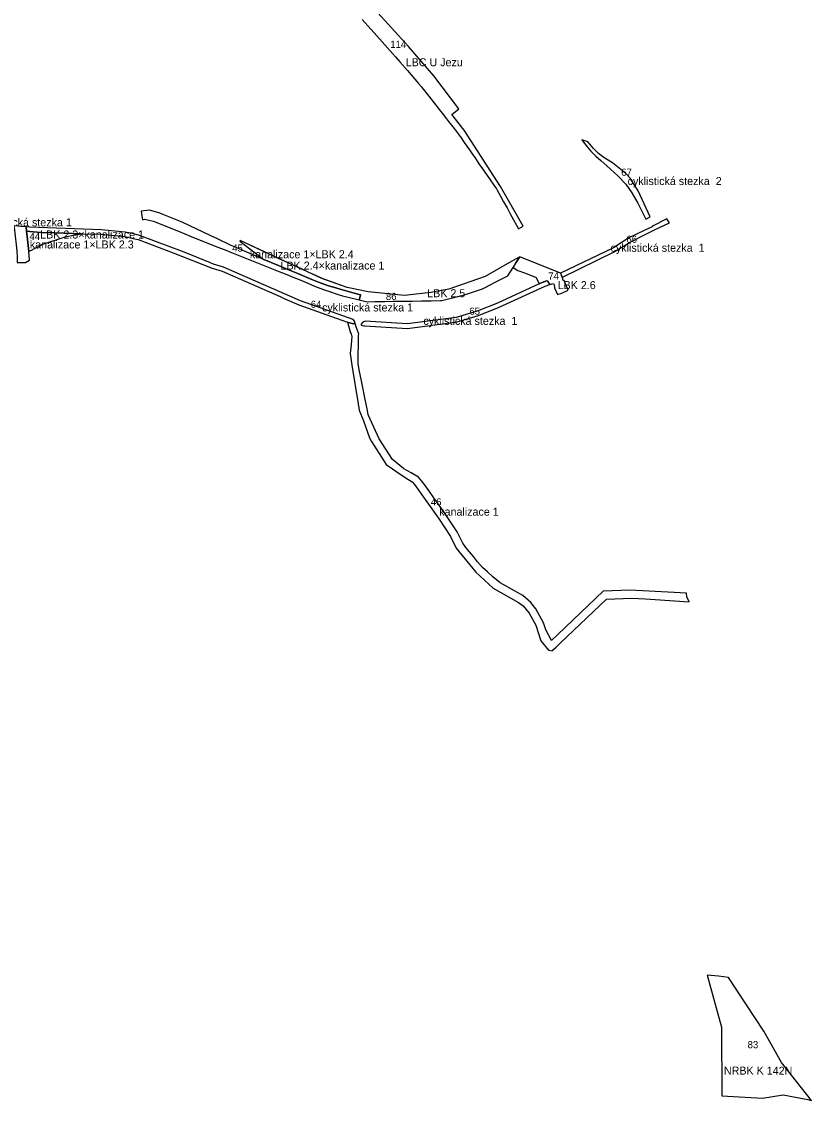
# Model space of a CAD drawing. Extents: x -535270 to -532834, y -1165802 to -1163869.
# Drawn here: x -533722 to -532834, y -1165802 to -1164589 of the extents above; entities that cross this region are included whole.
import ezdxf

# ---------------------------------------------------------------- set-up
doc = ezdxf.new("R2010")
doc.units = 0
for name, color, linetype in [('Level 51', 7, 'Continuous'), ('Level 57', 7, 'Continuous'), ('Level 59', 7, 'Continuous'), ('Level 60', 7, 'Continuous'), ('Level 61', 7, 'Continuous'), ('Level 62', 7, 'Continuous')]:
    doc.layers.add(name, color=color, linetype=linetype)

msp = doc.modelspace()

# ---------------------------------------------------------------- linework, layer by layer
at = {"layer": 'Level 51'}
for points in [[(-533076.2, -1164740.6), (-533070.5, -1164745.6), (-533063.9, -1164751.8), (-533051.6, -1164762.9), (-533042.4, -1164772.1), (-533035.7, -1164782.1), (-533028.9, -1164793.4), (-533020.2, -1164811.4), (-533015, -1164809.1), (-533028.6, -1164779.9), (-533037.8, -1164765.4), (-533042.7, -1164760.3), (-533057.7, -1164748.3), (-533059.3, -1164747.3), (-533067.1, -1164742.2), (-533073.2, -1164737.6), (-533078.8, -1164732.3), (-533082.7, -1164727.8), (-533085.2, -1164724.6), (-533088.7, -1164723.5), (-533092, -1164722.5), (-533090.2, -1164724.9), (-533085.8, -1164730.7), (-533081.8, -1164735.2), (-533076.2, -1164740.6)], [(-533508.9, -1164830.2), (-533541.2, -1164814.8), (-533558, -1164808.3), (-533563.9, -1164806), (-533566.5, -1164805), (-533577.8, -1164801.3), (-533587.3, -1164802.7), (-533586.5, -1164807.8), (-533585.8, -1164812.2), (-533583.6, -1164811.6), (-533573.3, -1164813.9), (-533568.8, -1164815.7), (-533545.2, -1164825.2), (-533531.1, -1164830.9), (-533502.4, -1164842.5), (-533497.2, -1164844.5), (-533491.2, -1164846.9), (-533487.7, -1164848.3), (-533431.5, -1164870.6), (-533428.4, -1164871.8), (-533423.5, -1164873.9), (-533415.9, -1164877.1), (-533408, -1164880.3), (-533400.1, -1164883.6), (-533392.6, -1164886.7), (-533386.5, -1164889.3), (-533381.4, -1164891), (-533373.5, -1164893.7), (-533369.1, -1164895.3), (-533366, -1164896.3), (-533360.9, -1164897.6), (-533353.2, -1164899.6), (-533343.8, -1164902), (-533342.3, -1164902.3), (-533341.7, -1164900), (-533340.8, -1164896.5), (-533348, -1164894.6), (-533355.6, -1164892.4), (-533363.8, -1164890.2), (-533368.5, -1164888.9), (-533376.8, -1164886.6), (-533387.9, -1164882.2), (-533395.4, -1164879.2), (-533403.4, -1164875.9), (-533411.2, -1164872.7), (-533418.9, -1164869.5), (-533426.8, -1164866.3), (-533432.8, -1164863.8), (-533449.3, -1164857), (-533482.5, -1164842.7), (-533486, -1164841.2), (-533502.2, -1164833.4), (-533508.9, -1164830.2)], [(-533012.9, -1164819.8), (-533013.1, -1164820), (-533021.8, -1164824.2), (-533039.3, -1164832.6), (-533056.5, -1164843.9), (-533116, -1164872.2), (-533114.8, -1164874.6), (-533114.4, -1164876.7), (-533113.9, -1164876.6), (-533055.7, -1164848.2), (-533054.7, -1164847.5), (-533037.7, -1164837.5), (-533037.4, -1164837.3), (-533036.8, -1164837), (-533019.4, -1164828.2), (-533011, -1164824), (-533010.3, -1164823.7), (-532993.6, -1164815.7), (-532996.3, -1164811.1), (-533011.7, -1164819.2), (-533012.9, -1164819.8)]]:
    msp.add_lwpolyline(points, dxfattribs=at)
for points in [[(-533425.9, -1164901), (-533410.2, -1164907.9), (-533368.1, -1164922.8), (-533355.4, -1164927.2), (-533349, -1164929.4), (-533346.6, -1164929), (-533347.4, -1164926.2), (-533349.1, -1164924.4), (-533390.2, -1164909.9), (-533408.4, -1164903.2), (-533494.7, -1164865.5), (-533506.1, -1164862), (-533509.4, -1164860.7), (-533541, -1164848), (-533589.2, -1164829.8), (-533593.1, -1164828.7), (-533598.9, -1164827.3), (-533603.5, -1164826.4), (-533605.3, -1164826.1), (-533632, -1164823.5), (-533712.8, -1164820.5), (-533716.6, -1164820.2), (-533716.1, -1164825.2), (-533708.7, -1164825.9), (-533699.2, -1164826.6), (-533684.5, -1164827), (-533654.5, -1164827.9), (-533632.4, -1164828.5), (-533605.8, -1164831.1), (-533596.5, -1164833.2), (-533590.8, -1164834.6), (-533551.4, -1164849.4), (-533507.7, -1164866.7), (-533496.4, -1164870.2), (-533431.1, -1164898.6)], [(-533704.3, -1164843), (-533700.8, -1164841.2), (-533699, -1164840.2), (-533671.6, -1164831.2), (-533654.5, -1164827.9), (-533684.5, -1164827), (-533699.2, -1164826.6), (-533708.7, -1164825.9), (-533716.1, -1164825.2), (-533716.1, -1164825.6), (-533715.5, -1164831), (-533713.8, -1164847.9)], [(-533133.3, -1164886.8), (-533127.9, -1164885.1), (-533130.3, -1164881.4), (-533131.8, -1164880.8), (-533136.5, -1164882.7), (-533140, -1164884.3), (-533186.9, -1164906.1), (-533209.6, -1164915), (-533233.2, -1164922.1), (-533288, -1164929.4), (-533335.4, -1164926.4), (-533338.3, -1164927.4), (-533340, -1164929.7), (-533340.1, -1164930.7), (-533337.2, -1164931.5), (-533335.9, -1164931.4), (-533287.8, -1164934.4), (-533232.1, -1164927), (-533208, -1164919.7), (-533184.9, -1164910.6)], [(-533330.5, -1165057.3), (-533328.6, -1165061.6), (-533311.9, -1165087.2), (-533304.7, -1165092.2), (-533299.9, -1165095.6), (-533290.7, -1165102), (-533282.9, -1165107), (-533280, -1165109.9), (-533252.3, -1165148.7), (-533239.7, -1165168.2), (-533233.2, -1165181.5), (-533211.2, -1165208.5), (-533191.6, -1165226.2), (-533163.2, -1165242.3), (-533157.9, -1165246.3), (-533151.3, -1165254.4), (-533143.8, -1165267.9), (-533138.1, -1165285.4), (-533129.6, -1165296), (-533125.2, -1165296.7), (-533125.2, -1165296.6), (-533120.8, -1165292.5), (-533116.4, -1165288.3), (-533064.2, -1165238.7), (-533036.3, -1165237.5), (-533020.4, -1165238.5), (-532971.5, -1165241.7), (-532973.8, -1165236), (-532974.3, -1165231.9), (-533023.4, -1165229.4), (-533038.2, -1165228.6), (-533068, -1165229.8), (-533119.1, -1165278.4), (-533126.2, -1165285.2), (-533132.6, -1165273.1), (-533135.2, -1165265.4), (-533143.8, -1165249.4), (-533149.3, -1165242.6), (-533158.3, -1165234.7), (-533167.6, -1165229.4), (-533183.9, -1165220.2), (-533192.1, -1165213.6), (-533198.2, -1165208.1), (-533203.7, -1165203.2), (-533209.1, -1165196.9), (-533213.9, -1165190.9), (-533218.3, -1165185.4), (-533222.3, -1165180.6), (-533225.9, -1165175.8), (-533232.2, -1165163.2), (-533239, -1165152.8), (-533245.6, -1165142.7), (-533252.3, -1165133.2), (-533258.3, -1165124.8), (-533264.1, -1165116.7), (-533269.9, -1165108.5), (-533275.6, -1165101.5), (-533283.8, -1165096.8), (-533291.9, -1165092.1), (-533292.5, -1165091.7), (-533304.9, -1165081.8), (-533319.9, -1165058.4), (-533331.7, -1165032.2), (-533332.2, -1165031), (-533333.6, -1165023), (-533333.9, -1165021.4), (-533336.2, -1165010.6), (-533338.2, -1165000.7), (-533340.1, -1164991.5), (-533340.1, -1164991.4), (-533341.9, -1164982.7), (-533343.6, -1164974.3), (-533343.3, -1164963.3), (-533343.1, -1164953), (-533342.9, -1164942.2), (-533342.8, -1164941), (-533344.5, -1164935.7), (-533345.5, -1164932.6), (-533346.6, -1164929), (-533349, -1164929.4), (-533355.4, -1164927.2), (-533354.9, -1164928.8), (-533353.4, -1164934.1), (-533351.9, -1164939.4), (-533351.3, -1164940.6), (-533350.5, -1164943.4), (-533351.3, -1164952.5), (-533352.3, -1164962.6), (-533350.7, -1164975.8), (-533343.4, -1165019.3), (-533342.2, -1165026.2), (-533337.6, -1165038.1)]]:
    msp.add_lwpolyline(points, close=True, dxfattribs=at)
at = {"layer": 'Level 57'}
for points in [[(-533258.2, -1164650.5), (-533286.9, -1164617.4), (-533325.2, -1164575.7)], [(-533339.1, -1164587.1), (-533322.4, -1164605.6), (-533313.5, -1164615.5), (-533304.8, -1164625.2), (-533301.3, -1164629.1), (-533296.5, -1164634.7), (-533288.1, -1164644.4), (-533279.8, -1164654.1), (-533275.6, -1164658.9), (-533272.7, -1164662.3), (-533271.4, -1164663.9), (-533264, -1164673.4), (-533256.1, -1164683.5), (-533250.9, -1164690.1), (-533249, -1164692.5), (-533244.1, -1164698.9), (-533241.9, -1164701.6), (-533237.1, -1164707.8), (-533232.8, -1164713.2), (-533230.2, -1164716.6), (-533228.4, -1164719.1), (-533224.2, -1164725.3), (-533218.4, -1164733.6), (-533214.4, -1164739.4), (-533212, -1164742.8), (-533207.6, -1164749.2), (-533203.5, -1164755.1), (-533199.2, -1164761.2), (-533195.1, -1164767.2), (-533190.9, -1164773.2), (-533187.9, -1164777.5), (-533187.1, -1164778.9), (-533183.4, -1164785.6), (-533179.9, -1164792), (-533176.1, -1164798.8), (-533172.4, -1164805.5), (-533168.8, -1164812.2), (-533165.3, -1164818.4), (-533163, -1164822.5), (-533157.8, -1164819.3), (-533183.3, -1164774.7), (-533224.1, -1164711.6), (-533238.1, -1164694.1), (-533230.1, -1164687.7), (-533258.2, -1164650.5)], [(-533342.3, -1164902.3), (-533341.7, -1164900), (-533340.8, -1164896.5), (-533348, -1164894.6), (-533355.6, -1164892.4), (-533363.8, -1164890.2), (-533368.5, -1164888.9), (-533376.8, -1164886.6), (-533387.9, -1164882.2), (-533395.4, -1164879.2), (-533403.4, -1164875.9), (-533411.2, -1164872.7), (-533418.9, -1164869.5), (-533426.8, -1164866.3), (-533432.8, -1164863.8), (-533449.3, -1164857), (-533482.5, -1164842.7), (-533486, -1164841.2), (-533502.2, -1164833.4), (-533508.9, -1164830.2), (-533541.2, -1164814.8), (-533558, -1164808.3), (-533563.9, -1164806), (-533566.5, -1164805), (-533577.8, -1164801.3), (-533587.3, -1164802.7), (-533586.5, -1164807.8), (-533585.8, -1164812.2), (-533583.6, -1164811.6), (-533573.3, -1164813.9), (-533568.8, -1164815.7), (-533545.2, -1164825.2), (-533531.1, -1164830.9), (-533502.4, -1164842.5), (-533497.2, -1164844.5), (-533491.2, -1164846.9), (-533487.7, -1164848.3), (-533431.5, -1164870.6), (-533428.4, -1164871.8), (-533423.5, -1164873.9), (-533415.9, -1164877.1), (-533408, -1164880.3), (-533400.1, -1164883.6), (-533392.6, -1164886.7), (-533386.5, -1164889.3), (-533381.4, -1164891), (-533373.5, -1164893.7), (-533369.1, -1164895.3), (-533366, -1164896.3), (-533360.9, -1164897.6), (-533353.2, -1164899.6), (-533343.8, -1164902), (-533342.3, -1164902.3)], [(-533654.5, -1164827.9), (-533684.5, -1164827), (-533699.2, -1164826.6), (-533708.7, -1164825.9), (-533716.1, -1164825.2), (-533716.1, -1164825.6), (-533715.5, -1164831), (-533713.8, -1164847.9), (-533704.3, -1164843), (-533700.8, -1164841.2), (-533699, -1164840.2), (-533671.6, -1164831.2), (-533654.5, -1164827.9)], [(-533128.7, -1164883.8), (-533127.9, -1164885.1), (-533123.8, -1164883.9), (-533123.2, -1164885.5), (-533122.9, -1164888.8), (-533119.4, -1164896.4), (-533114.4, -1164894.8), (-533107.5, -1164891.5), (-533111.8, -1164880.4), (-533113, -1164880.4), (-533113.9, -1164876.6), (-533114.4, -1164876.7), (-533114.8, -1164874.6), (-533116, -1164872.2), (-533161.7, -1164853.8), (-533166.1, -1164860.6), (-533169.3, -1164865.8), (-533163.8, -1164869.1), (-533155.4, -1164872.4), (-533143.4, -1164877), (-533140, -1164884.3), (-533136.5, -1164882.7), (-533131.8, -1164880.8), (-533130.3, -1164881.4), (-533128.7, -1164883.8)], [(-532887.3, -1165724.4), (-532927.2, -1165664.1), (-532938.5, -1165662.6), (-532951, -1165661.3), (-532935.1, -1165719.9), (-532934.7, -1165797.1), (-532888.9, -1165799.8), (-532865.5, -1165795.7), (-532838, -1165801.3), (-532833.9, -1165802.2), (-532867.5, -1165759.6), (-532887.3, -1165724.4)]]:
    msp.add_lwpolyline(points, dxfattribs=at)
msp.add_lwpolyline([(-533426.8, -1164866.3), (-533418.9, -1164869.5), (-533411.2, -1164872.7), (-533403.4, -1164875.9), (-533395.4, -1164879.2), (-533387.9, -1164882.2), (-533376.8, -1164886.6), (-533368.5, -1164888.9), (-533363.8, -1164890.2), (-533355.6, -1164892.4), (-533348, -1164894.6), (-533340.8, -1164896.5), (-533341.7, -1164900), (-533342.3, -1164902.3), (-533334.9, -1164904.2), (-533333.9, -1164904.5), (-533324.7, -1164904.3), (-533313.4, -1164904.1), (-533303.9, -1164903.9), (-533296.3, -1164903.8), (-533293.4, -1164903.8), (-533282.6, -1164903.6), (-533272.3, -1164903.4), (-533261.5, -1164903.2), (-533251, -1164903), (-533249.4, -1164903), (-533235.8, -1164899.6), (-533225.4, -1164897.1), (-533220.5, -1164895.4), (-533203.5, -1164889.7), (-533200, -1164887.9), (-533189.5, -1164882.5), (-533175.2, -1164875.1), (-533169.3, -1164865.8), (-533166.1, -1164860.6), (-533161.7, -1164853.8), (-533170.8, -1164858.6), (-533200.7, -1164876.2), (-533241.5, -1164890.3), (-533261.9, -1164894.1), (-533291.4, -1164897.2), (-533332.2, -1164893.4), (-533355.9, -1164888.3), (-533383.8, -1164878.3), (-533391, -1164875), (-533398.7, -1164871.4), (-533406.2, -1164867.9), (-533413.7, -1164864.5), (-533421.2, -1164861), (-533432.1, -1164856), (-533476.1, -1164835.7), (-533476.6, -1164836.3), (-533449.3, -1164857), (-533432.8, -1164863.8)], close=True, dxfattribs=at)
at = {"layer": 'Level 59'}
for points in [[(-533339.1, -1164587.1), (-533322.4, -1164605.6), (-533313.5, -1164615.5), (-533304.8, -1164625.2), (-533301.3, -1164629.1), (-533296.5, -1164634.7), (-533288.1, -1164644.4), (-533279.8, -1164654.1), (-533275.6, -1164658.9), (-533272.7, -1164662.3), (-533271.4, -1164663.9), (-533264, -1164673.4), (-533256.1, -1164683.5), (-533250.9, -1164690.1), (-533249, -1164692.5), (-533244.1, -1164698.9), (-533241.9, -1164701.6), (-533237.1, -1164707.8), (-533232.8, -1164713.2), (-533230.2, -1164716.6), (-533228.4, -1164719.1), (-533224.2, -1164725.3), (-533218.4, -1164733.6), (-533214.4, -1164739.4), (-533212, -1164742.8), (-533207.6, -1164749.2), (-533203.5, -1164755.1), (-533199.2, -1164761.2), (-533195.1, -1164767.2), (-533190.9, -1164773.2), (-533187.9, -1164777.5), (-533187.1, -1164778.9), (-533183.4, -1164785.6), (-533179.9, -1164792), (-533176.1, -1164798.8), (-533172.4, -1164805.5), (-533168.8, -1164812.2), (-533165.3, -1164818.4), (-533163, -1164822.5), (-533157.8, -1164819.3), (-533183.3, -1164774.7), (-533224.1, -1164711.6), (-533238.1, -1164694.1), (-533230.1, -1164687.7), (-533258.2, -1164650.5), (-533286.9, -1164617.4), (-533325.2, -1164575.7)], [(-533085.8, -1164730.7), (-533081.8, -1164735.2), (-533076.2, -1164740.6), (-533070.5, -1164745.6), (-533063.9, -1164751.8), (-533051.6, -1164762.9), (-533042.4, -1164772.1), (-533035.7, -1164782.1), (-533028.9, -1164793.4), (-533020.2, -1164811.4), (-533015, -1164809.1), (-533028.6, -1164779.9), (-533037.8, -1164765.4), (-533042.7, -1164760.3), (-533057.7, -1164748.3), (-533059.3, -1164747.3), (-533067.1, -1164742.2), (-533073.2, -1164737.6), (-533078.8, -1164732.3), (-533082.7, -1164727.8), (-533085.2, -1164724.6), (-533088.7, -1164723.5), (-533092, -1164722.5), (-533090.2, -1164724.9), (-533085.8, -1164730.7)], [(-533113, -1164880.4), (-533113.9, -1164876.6), (-533055.7, -1164848.2), (-533054.7, -1164847.5), (-533037.7, -1164837.5), (-533037.4, -1164837.3), (-533036.8, -1164837), (-533019.4, -1164828.2), (-533011, -1164824), (-533010.3, -1164823.7), (-532993.6, -1164815.7), (-532996.3, -1164811.1), (-533011.7, -1164819.2), (-533012.9, -1164819.8), (-533013.1, -1164820), (-533021.8, -1164824.2), (-533039.3, -1164832.6), (-533056.5, -1164843.9), (-533116, -1164872.2), (-533161.7, -1164853.8), (-533170.8, -1164858.6), (-533200.7, -1164876.2), (-533241.5, -1164890.3), (-533261.9, -1164894.1), (-533291.4, -1164897.2), (-533332.2, -1164893.4), (-533355.9, -1164888.3), (-533384.1, -1164878.1), (-533476.1, -1164835.7), (-533476.6, -1164836.3), (-533449.3, -1164857), (-533482.5, -1164842.7), (-533486, -1164841.2), (-533502.2, -1164833.4), (-533508.9, -1164830.2), (-533541.2, -1164814.8), (-533558, -1164808.3), (-533563.9, -1164806), (-533566.5, -1164805), (-533577.8, -1164801.3), (-533587.3, -1164802.7), (-533586.5, -1164807.8), (-533585.8, -1164812.2), (-533583.6, -1164811.6), (-533573.3, -1164813.9), (-533568.8, -1164815.7), (-533545.2, -1164825.2), (-533531.1, -1164830.9), (-533502.4, -1164842.5), (-533497.2, -1164844.5), (-533491.2, -1164846.9), (-533487.7, -1164848.3), (-533431.5, -1164870.6), (-533428.4, -1164871.8), (-533423.5, -1164873.9), (-533415.9, -1164877.1), (-533408, -1164880.3), (-533400.1, -1164883.6), (-533392.6, -1164886.7), (-533386.5, -1164889.3), (-533381.4, -1164891), (-533373.5, -1164893.7), (-533369.1, -1164895.3), (-533366, -1164896.3), (-533360.9, -1164897.6), (-533353.2, -1164899.6), (-533343.8, -1164902), (-533342.3, -1164902.3), (-533334.9, -1164904.2), (-533333.9, -1164904.5), (-533324.7, -1164904.3), (-533313.4, -1164904.1), (-533303.9, -1164903.9), (-533296.3, -1164903.8), (-533293.4, -1164903.8), (-533282.6, -1164903.6), (-533272.3, -1164903.4), (-533261.5, -1164903.2), (-533251, -1164903), (-533249.4, -1164903), (-533235.8, -1164899.6), (-533225.4, -1164897.1), (-533220.5, -1164895.4), (-533203.5, -1164889.7), (-533200, -1164887.9), (-533189.5, -1164882.5), (-533175.2, -1164875.1), (-533169.3, -1164865.8), (-533163.8, -1164869.1), (-533155.4, -1164872.4), (-533143.4, -1164877), (-533140, -1164884.3), (-533186.9, -1164906.1), (-533209.6, -1164915), (-533233.2, -1164922.1), (-533288, -1164929.4), (-533335.4, -1164926.4), (-533338.3, -1164927.4), (-533340, -1164929.7), (-533340.1, -1164930.7), (-533337.2, -1164931.5), (-533335.9, -1164931.4), (-533287.8, -1164934.4), (-533232.1, -1164927), (-533208, -1164919.7), (-533184.9, -1164910.6), (-533133.3, -1164886.8), (-533127.9, -1164885.1), (-533123.8, -1164883.9), (-533123.2, -1164885.5), (-533122.9, -1164888.8), (-533119.4, -1164896.4), (-533114.4, -1164894.8), (-533107.5, -1164891.5), (-533111.8, -1164880.4), (-533113, -1164880.4)], [(-532867.5, -1165759.6), (-532887.3, -1165724.4), (-532927.2, -1165664.1), (-532938.5, -1165662.6), (-532951, -1165661.3), (-532935.1, -1165719.9), (-532934.7, -1165797.1), (-532888.9, -1165799.8), (-532865.5, -1165795.7), (-532838, -1165801.3), (-532833.9, -1165802.2), (-532867.5, -1165759.6)]]:
    msp.add_lwpolyline(points, dxfattribs=at)
msp.add_lwpolyline([(-533345.5, -1164932.6), (-533346.6, -1164929), (-533347.4, -1164926.2), (-533349.1, -1164924.4), (-533390.2, -1164909.9), (-533408.4, -1164903.2), (-533494.7, -1164865.5), (-533506.1, -1164862), (-533509.4, -1164860.7), (-533541, -1164848), (-533589.2, -1164829.8), (-533593.1, -1164828.7), (-533598.9, -1164827.3), (-533603.5, -1164826.4), (-533605.3, -1164826.1), (-533632, -1164823.5), (-533712.8, -1164820.5), (-533716.6, -1164820.2), (-533716.1, -1164825.2), (-533716.1, -1164825.6), (-533715.5, -1164831), (-533713.8, -1164847.9), (-533704.3, -1164843), (-533700.8, -1164841.2), (-533699, -1164840.2), (-533671.6, -1164831.2), (-533654.5, -1164827.9), (-533632.4, -1164828.5), (-533605.8, -1164831.1), (-533596.5, -1164833.2), (-533590.8, -1164834.6), (-533551.4, -1164849.4), (-533507.7, -1164866.7), (-533496.4, -1164870.2), (-533431.1, -1164898.6), (-533425.9, -1164901), (-533410.2, -1164907.9), (-533368.1, -1164922.8), (-533355.4, -1164927.2), (-533354.9, -1164928.8), (-533353.4, -1164934.1), (-533351.9, -1164939.4), (-533351.3, -1164940.6), (-533350.5, -1164943.4), (-533351.3, -1164952.5), (-533352.3, -1164962.6), (-533350.7, -1164975.8), (-533343.4, -1165019.3), (-533342.2, -1165026.2), (-533337.6, -1165038.1), (-533330.5, -1165057.3), (-533328.6, -1165061.6), (-533311.9, -1165087.2), (-533304.7, -1165092.2), (-533299.9, -1165095.6), (-533290.7, -1165102), (-533282.9, -1165107), (-533280, -1165109.9), (-533252.3, -1165148.7), (-533239.7, -1165168.2), (-533233.2, -1165181.5), (-533211.2, -1165208.5), (-533191.6, -1165226.2), (-533163.2, -1165242.3), (-533157.9, -1165246.3), (-533151.3, -1165254.4), (-533143.8, -1165267.9), (-533138.1, -1165285.4), (-533129.6, -1165296), (-533125.2, -1165296.7), (-533125.2, -1165296.6), (-533120.8, -1165292.5), (-533116.4, -1165288.3), (-533064.2, -1165238.7), (-533036.3, -1165237.5), (-533020.4, -1165238.5), (-532971.5, -1165241.7), (-532973.8, -1165236), (-532974.3, -1165231.9), (-533023.4, -1165229.4), (-533038.2, -1165228.6), (-533068, -1165229.8), (-533119.1, -1165278.4), (-533126.2, -1165285.2), (-533132.6, -1165273.1), (-533135.2, -1165265.4), (-533143.8, -1165249.4), (-533149.3, -1165242.6), (-533158.3, -1165234.7), (-533167.6, -1165229.4), (-533183.9, -1165220.2), (-533192.1, -1165213.6), (-533198.2, -1165208.1), (-533203.7, -1165203.2), (-533209.1, -1165196.9), (-533213.9, -1165190.9), (-533218.3, -1165185.4), (-533222.3, -1165180.6), (-533225.9, -1165175.8), (-533232.2, -1165163.2), (-533239, -1165152.8), (-533245.6, -1165142.7), (-533252.3, -1165133.2), (-533258.3, -1165124.8), (-533264.1, -1165116.7), (-533269.9, -1165108.5), (-533275.6, -1165101.5), (-533283.8, -1165096.8), (-533291.9, -1165092.1), (-533292.5, -1165091.7), (-533304.9, -1165081.8), (-533319.9, -1165058.4), (-533331.7, -1165032.2), (-533332.2, -1165031), (-533333.6, -1165023), (-533333.9, -1165021.4), (-533336.2, -1165010.6), (-533338.2, -1165000.7), (-533340.1, -1164991.5), (-533340.1, -1164991.4), (-533341.9, -1164982.7), (-533343.6, -1164974.3), (-533343.3, -1164963.3), (-533343.1, -1164953), (-533342.9, -1164942.2), (-533342.8, -1164941), (-533344.5, -1164935.7)], close=True, dxfattribs=at)
at = {"layer": 'Level 60'}
msp.add_lwpolyline([(-533722.7, -1164819.8), (-533726, -1164819.6), (-533730.5, -1164819.2), (-533730, -1164821.1), (-533729.7, -1164824.1), (-533727.1, -1164847.2), (-533726.9, -1164854), (-533726.7, -1164859.2), (-533726.9, -1164860.2), (-533724, -1164860.2), (-533717.5, -1164860.1), (-533712.8, -1164857.6), (-533713.8, -1164847.9), (-533715.5, -1164831), (-533716.1, -1164825.6), (-533716.1, -1164825.2), (-533716.6, -1164820.2)], close=True, dxfattribs=at)

# ---------------------------------------------------------------- texts
at = {"layer": 'Level 51'}
for s, p in [('cyklistická stezka  2', (-533040.5, -1164773.2)), ('cyklistická stezka 1', (-533767.6, -1164819.6)), ('kanalizace 1×LBK 2.3', (-533712.5, -1164844.5)), ('cyklistická stezka  1', (-533059.7, -1164848.2)), ('kanalizace 1×LBK 2.4', (-533465.2, -1164855.5)), ('cyklistická stezka 1', (-533384, -1164915.3)), ('cyklistická stezka  1', (-533270.1, -1164930.4)), ('kanalizace 1', (-533252.3, -1165144.9))]:
    msp.add_text(s, height=9, dxfattribs=at).set_placement(p)
at = {"layer": 'Level 57'}
for s, p in [('LBC U Jezu', (-533290, -1164639.7)), ('LBK 2.3×kanalizace 1', (-533700.9, -1164833.3)), ('LBK 2.4×kanalizace 1', (-533430.7, -1164868.2)), ('LBK 2.5', (-533265.8, -1164899.3)), ('LBK 2.6', (-533119.2, -1164890.2))]:
    msp.add_text(s, height=9, dxfattribs=at).set_placement(p)
msp.add_text('NRBK K 142N', height=9, rotation=359.8716, dxfattribs=at).set_placement((-532932.3, -1165773.1))
at = {"layer": 'Level 61'}
for s, p in [('67', (-533047.7, -1164762.8)), ('44', (-533712.9, -1164835)), ('66', (-533041.9, -1164838.2)), ('45', (-533485, -1164848)), ('64', (-533396.7, -1164911.2)), ('65', (-533218.4, -1164919)), ('46', (-533261.7, -1165133.4))]:
    msp.add_text(s, height=8, dxfattribs=at).set_placement(p)
at = {"layer": 'Level 62'}
for s, p in [('114', (-533307.3, -1164619)), ('44', (-533712.9, -1164835)), ('45', (-533485, -1164848)), ('74', (-533129.7, -1164879.4)), ('86', (-533312.2, -1164902.4)), ('83', (-532905.6, -1165743.5))]:
    msp.add_text(s, height=8, dxfattribs=at).set_placement(p)

doc.saveas('drawing.dxf')
